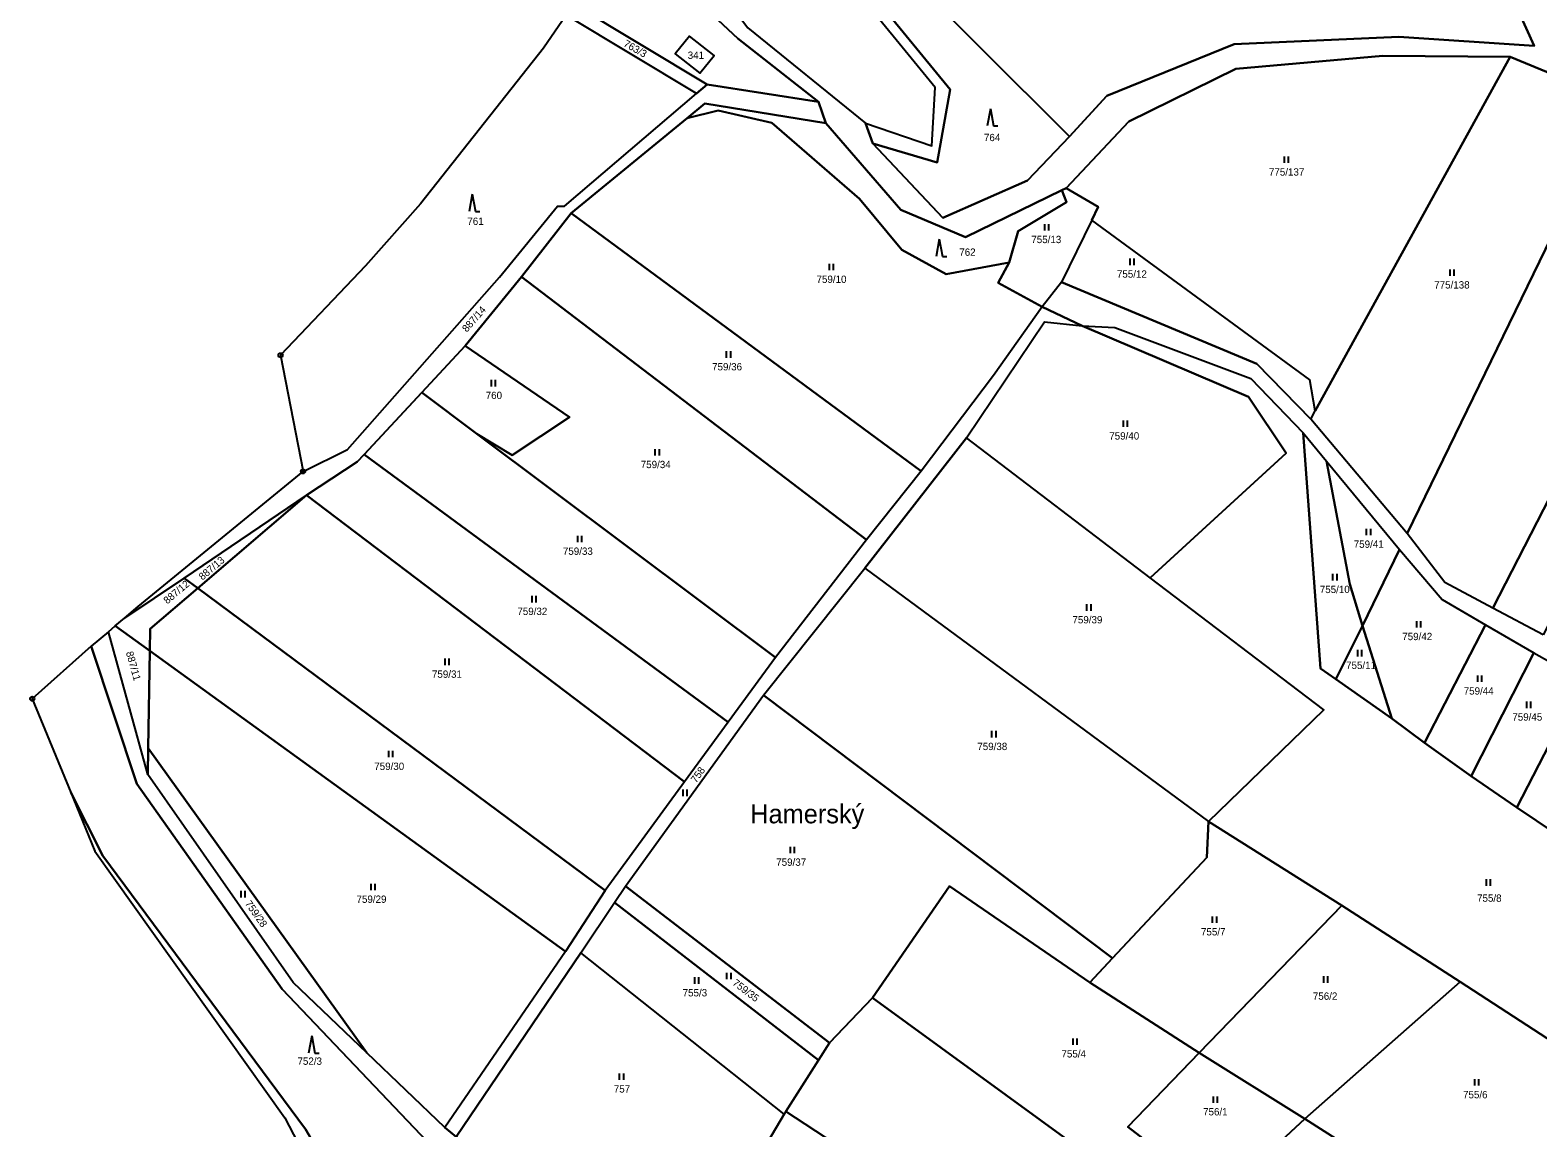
# Model space of a CAD drawing. Extents: x -654083 to -650132, y -1099819 to -1096699.
# Drawn here: x -653842.7 to -653492.6, y -1098231 to -1097976.1 of the extents above; entities that cross this region are included whole.
import ezdxf

# ---------------------------------------------------------------- set-up
doc = ezdxf.new("R2010")
doc.units = 0
for name, color, linetype in [('Geodetické body', 7, 'Continuous'), ('Názvy', 7, 'Continuous'), ('Obvody jako plochy', 7, 'Continuous'), ('Parcelní čísla', 7, 'Continuous'), ('Značky kultur', 7, 'Continuous')]:
    doc.layers.add(name, color=color, linetype=linetype)

msp = doc.modelspace()

# ---------------------------------------------------------------- linework, layer by layer
at = {"layer": 'Geodetické body'}
for centre, radius in [((-653784.54, -1098051.6), 0.5), ((-653784.54, -1098051.6), 0.001), ((-653779.31, -1098078.59), 0.5), ((-653779.31, -1098078.59), 0.001), ((-653842.18, -1098131.36), 0.5), ((-653842.18, -1098131.36), 0.001)]:
    msp.add_circle(centre, radius, dxfattribs=at)
at = {"layer": 'Obvody jako plochy'}
for points in [[(-653713.62, -1097930.33), (-653706.55, -1097940.57), (-653697.49, -1097947.08), (-653675.99, -1097975.54), (-653648.7, -1097997.71), (-653633.3, -1098002.98), (-653632.53, -1097989.46), (-653653.11, -1097964.2), (-653667.52, -1097949), (-653667.58, -1097933.88), (-653666.3, -1097931.63), (-653679.22, -1097917.1), (-653687.31, -1097908.47), (-653704.35, -1097912.36)], [(-653649.71, -1097952.26), (-653642.8, -1097959.41), (-653601.35, -1098000.78), (-653611.1, -1098011.02), (-653630.75, -1098019.66), (-653647, -1098002.44), (-653632.03, -1098006.86), (-653629.06, -1097989.93), (-653663.58, -1097947.68)], [(-653703.46, -1097954.62), (-653678.31, -1097978.03), (-653659.65, -1097992.78), (-653685.44, -1097988.72), (-653716.54, -1097970.07), (-653709.82, -1097960.08)], [(-653642.8, -1097959.41), (-653496.77, -1097972.37), (-653493.43, -1097979.77), (-653524.85, -1097977.7), (-653563.09, -1097979.4), (-653592.66, -1097991.35), (-653601.35, -1098000.78)], [(-653784.54, -1098051.6), (-653779.31, -1098078.59), (-653768.96, -1098073.49), (-653733.67, -1098033.51), (-653720.21, -1098016.99), (-653718.63, -1098017), (-653687.93, -1097990.83), (-653718.24, -1097972.6), (-653723.44, -1097980.32), (-653752.03, -1098016.42), (-653764.83, -1098030.84)], [(-653718.24, -1097972.6), (-653716.54, -1097970.07), (-653685.44, -1097988.72), (-653687.93, -1097990.83)], [(-653683.87, -1097982.01), (-653689.53, -1097977.49), (-653692.91, -1097981.61), (-653687.19, -1097986.07)], [(-653689.53, -1097977.49), (-653692.91, -1097981.61), (-653687.19, -1097986.07), (-653683.87, -1097982.01)], [(-653683.87, -1097982.01), (-653689.53, -1097977.49), (-653692.91, -1097981.61), (-653687.19, -1097986.07)], [(-653562.68, -1097985.1), (-653528.58, -1097982.07), (-653499, -1097982.28), (-653544.24, -1098064.55), (-653545.5, -1098057.32), (-653596.14, -1098020.25), (-653594.63, -1098017.16), (-653602.07, -1098012.79), (-653587.53, -1097997.31)], [(-653474.06, -1097992.64), (-653522.9, -1098093.01), (-653545.29, -1098066.46), (-653544.24, -1098064.55), (-653499, -1097982.28)], [(-653766.71, -1098076.38), (-653778.54, -1098084.12), (-653806.95, -1098103.34), (-653820.78, -1098112.69), (-653817.58, -1098109.96), (-653779.31, -1098078.59), (-653768.96, -1098073.49), (-653733.67, -1098033.51), (-653720.21, -1098016.99), (-653718.63, -1098017), (-653687.93, -1097990.83), (-653685.44, -1097988.72), (-653659.65, -1097992.78), (-653657.92, -1097997.75), (-653685.97, -1097993.14), (-653690.13, -1097996.58), (-653717.07, -1098018.65), (-653728.58, -1098033.36), (-653741.63, -1098049.4), (-653751.75, -1098060.24), (-653765.08, -1098074.62)], [(-653657.92, -1097997.75), (-653640.48, -1098017.81), (-653625.48, -1098024.2), (-653603.11, -1098013.28), (-653602.06, -1098016.08), (-653613.28, -1098022.81), (-653615.34, -1098030.08), (-653629.95, -1098032.79), (-653640.24, -1098027.1), (-653650.11, -1098015.27), (-653670.41, -1097997.63), (-653682.92, -1097994.74), (-653690.13, -1097996.58), (-653685.97, -1097993.14)], [(-653448.67, -1098004.49), (-653503.03, -1098110.31), (-653514.16, -1098104.36), (-653522.9, -1098093.01), (-653474.06, -1097992.64)], [(-653640.24, -1098027.1), (-653629.95, -1098032.79), (-653615.34, -1098030.08), (-653617.92, -1098034.79), (-653607.69, -1098040.36), (-653618.97, -1098056.31), (-653635.8, -1098078.5), (-653717.07, -1098018.65), (-653690.13, -1097996.58), (-653682.92, -1097994.74), (-653670.41, -1097997.63), (-653650.11, -1098015.27)], [(-653491.36, -1098116.55), (-653503.03, -1098110.31), (-653448.67, -1098004.49), (-653437.16, -1098010.24)], [(-653603.11, -1098013.28), (-653602.07, -1098012.79), (-653594.63, -1098017.16), (-653596.14, -1098020.25), (-653603.2, -1098034.64), (-653607.69, -1098040.36), (-653617.92, -1098034.79), (-653615.34, -1098030.08), (-653613.28, -1098022.81), (-653602.06, -1098016.08)], [(-653717.07, -1098018.65), (-653635.8, -1098078.5), (-653648.49, -1098094.45), (-653728.58, -1098033.36)], [(-653545.29, -1098066.46), (-653544.24, -1098064.55), (-653545.5, -1098057.32), (-653596.14, -1098020.25), (-653603.2, -1098034.64), (-653557.83, -1098053.58)], [(-653728.58, -1098033.36), (-653648.49, -1098094.45), (-653669.6, -1098121.79), (-653738.93, -1098069.85), (-653730.77, -1098074.77), (-653717.44, -1098065.97), (-653741.63, -1098049.4)], [(-653618.97, -1098056.31), (-653635.8, -1098078.5), (-653648.49, -1098094.45), (-653669.6, -1098121.79), (-653680.58, -1098136.79), (-653690.76, -1098150.69), (-653709.18, -1098175.93), (-653718.33, -1098190.03), (-653746.37, -1098230.94), (-653743.73, -1098233.12), (-653714.84, -1098190.36), (-653706.96, -1098178.69), (-653704.43, -1098174.89), (-653672.35, -1098130.56), (-653648.86, -1098101.05), (-653625.26, -1098070.79), (-653607.11, -1098043.87), (-653598.42, -1098044.74), (-653607.69, -1098040.36)], [(-653598.42, -1098044.74), (-653559.78, -1098061.29), (-653551.01, -1098074.32), (-653582.6, -1098103.32), (-653625.26, -1098070.79), (-653607.11, -1098043.87)], [(-653526.47, -1098135.95), (-653518.87, -1098141.6), (-653508.05, -1098149.35), (-653498.93, -1098155.64), (-653497.41, -1098156.63), (-653488.24, -1098162.8), (-653478.25, -1098170.57), (-653468.63, -1098177.08), (-653458.96, -1098184.59), (-653444.09, -1098197.38), (-653468.56, -1098224.39), (-653510.59, -1098197.1), (-653538.11, -1098179.34), (-653569.01, -1098159.89), (-653542.28, -1098133.96), (-653582.6, -1098103.32), (-653551.01, -1098074.32), (-653559.78, -1098061.29), (-653598.42, -1098044.74), (-653590.78, -1098045.19), (-653559.18, -1098057.02), (-653547.07, -1098069.66), (-653543, -1098124.32), (-653539.45, -1098126.81)], [(-653717.44, -1098065.97), (-653730.77, -1098074.77), (-653738.93, -1098069.85), (-653751.75, -1098060.24), (-653741.63, -1098049.4)], [(-653669.6, -1098121.79), (-653680.58, -1098136.79), (-653765.08, -1098074.62), (-653751.75, -1098060.24), (-653738.93, -1098069.85)], [(-653536.26, -1098104.78), (-653533.27, -1098114.41), (-653539.45, -1098126.81), (-653543, -1098124.32), (-653547.07, -1098069.66), (-653541.65, -1098076.21)], [(-653569.01, -1098159.89), (-653542.28, -1098133.96), (-653582.6, -1098103.32), (-653625.26, -1098070.79), (-653648.86, -1098101.05)], [(-653765.08, -1098074.62), (-653680.58, -1098136.79), (-653690.76, -1098150.69), (-653778.54, -1098084.12), (-653766.71, -1098076.38)], [(-653541.65, -1098076.21), (-653524.67, -1098096.75), (-653533.27, -1098114.41), (-653536.26, -1098104.78)], [(-653778.54, -1098084.12), (-653803.78, -1098105.68), (-653806.95, -1098103.34)], [(-653778.54, -1098084.12), (-653690.76, -1098150.69), (-653709.18, -1098175.93), (-653803.78, -1098105.68)], [(-653524.67, -1098096.75), (-653514.76, -1098108.32), (-653504.7, -1098114.18), (-653518.87, -1098141.6), (-653526.47, -1098135.95), (-653533.27, -1098114.41)], [(-653569.01, -1098159.89), (-653569.45, -1098168.26), (-653591.35, -1098191.64), (-653672.35, -1098130.56), (-653648.86, -1098101.05)], [(-653814.81, -1098115.11), (-653814.89, -1098120.27), (-653822.9, -1098114.47), (-653820.78, -1098112.69), (-653806.95, -1098103.34), (-653803.78, -1098105.68)], [(-653709.18, -1098175.93), (-653718.33, -1098190.03), (-653814.89, -1098120.27), (-653814.81, -1098115.11), (-653803.78, -1098105.68)], [(-653814.89, -1098120.27), (-653815.24, -1098142.84), (-653815.33, -1098148.98), (-653824.49, -1098115.81), (-653822.9, -1098114.47)], [(-653533.27, -1098114.41), (-653526.47, -1098135.95), (-653539.45, -1098126.81)], [(-653504.7, -1098114.18), (-653493.48, -1098120.72), (-653508.05, -1098149.35), (-653518.87, -1098141.6)], [(-653721.27, -1098267.91), (-653711.82, -1098254.28), (-653728.34, -1098247.4), (-653747.42, -1098237.45), (-653784.16, -1098198.82), (-653817.94, -1098151.09), (-653828.49, -1098119.16), (-653842.18, -1098131.36), (-653833.25, -1098153.1), (-653825.81, -1098167.82), (-653778.72, -1098231.33), (-653763.42, -1098257.49), (-653742.27, -1098284.25)], [(-653814.89, -1098120.27), (-653718.33, -1098190.03), (-653746.37, -1098230.94), (-653764.5, -1098213.59), (-653815.24, -1098142.84)], [(-653482.17, -1098127.04), (-653497.41, -1098156.63), (-653498.93, -1098155.64), (-653508.05, -1098149.35), (-653493.48, -1098120.72)], [(-653482.17, -1098127.04), (-653472.69, -1098132.34), (-653488.24, -1098162.8), (-653497.41, -1098156.63)], [(-653629.2, -1098174.91), (-653647.07, -1098200.83), (-653657.02, -1098211.29), (-653704.43, -1098174.89), (-653672.35, -1098130.56), (-653591.35, -1098191.64), (-653596.62, -1098197.26)], [(-653815.24, -1098142.84), (-653764.5, -1098213.59), (-653781.58, -1098197.23), (-653815.33, -1098148.98)], [(-653827.67, -1098166.73), (-653783.54, -1098228.67), (-653767.24, -1098260.09), (-653753.1, -1098273.36), (-653743.69, -1098285.49), (-653742.27, -1098284.25), (-653763.42, -1098257.49), (-653778.72, -1098231.33), (-653825.81, -1098167.82), (-653833.25, -1098153.1)], [(-653569.01, -1098159.89), (-653538.11, -1098179.34), (-653571.22, -1098213.59), (-653596.62, -1098197.26), (-653591.35, -1098191.64), (-653569.45, -1098168.26)], [(-653657.02, -1098211.29), (-653659.63, -1098215.26), (-653706.96, -1098178.69), (-653704.43, -1098174.89)], [(-653546.7, -1098228.92), (-653502.41, -1098257.19), (-653526.27, -1098282.15), (-653530.29, -1098285.81), (-653543.55, -1098284.07), (-653600.1, -1098235.04), (-653647.07, -1098200.83), (-653629.2, -1098174.91), (-653596.62, -1098197.26), (-653571.22, -1098213.59), (-653587.81, -1098230.74), (-653566.43, -1098247.25)], [(-653706.96, -1098178.69), (-653659.63, -1098215.26), (-653667.18, -1098227.19), (-653667.58, -1098227.83), (-653714.84, -1098190.36)], [(-653510.59, -1098197.1), (-653546.7, -1098228.92), (-653571.22, -1098213.59), (-653538.11, -1098179.34)], [(-653667.58, -1098227.83), (-653714.84, -1098190.36), (-653743.73, -1098233.12), (-653729.84, -1098242.69), (-653706.46, -1098252.31), (-653684.02, -1098255.61)], [(-653510.59, -1098197.1), (-653468.56, -1098224.39), (-653476.06, -1098232.31), (-653502.41, -1098257.19), (-653546.7, -1098228.92)], [(-653556.04, -1098300.72), (-653566.03, -1098298.04), (-653625.84, -1098254.28), (-653667.18, -1098227.19), (-653659.63, -1098215.26), (-653657.02, -1098211.29), (-653647.07, -1098200.83), (-653600.1, -1098235.04), (-653543.55, -1098284.07)], [(-653571.22, -1098213.59), (-653546.7, -1098228.92), (-653566.43, -1098247.25), (-653587.81, -1098230.74)], [(-653629.97, -1098294.65), (-653582.55, -1098325.18), (-653566.03, -1098298.04), (-653625.84, -1098254.28), (-653667.18, -1098227.19), (-653667.58, -1098227.83), (-653684.02, -1098255.61)]]:
    msp.add_lwpolyline(points, close=True, dxfattribs=at)
for points in [[(-653663.58, -1097947.68), (-653629.06, -1097989.93), (-653632.03, -1098006.86), (-653647, -1098002.44), (-653648.7, -1097997.71), (-653633.3, -1098002.98), (-653632.53, -1097989.46), (-653653.11, -1097964.2)], [(-653474.06, -1097992.64), (-653499, -1097982.28), (-653528.58, -1097982.07), (-653562.68, -1097985.1), (-653587.53, -1097997.31), (-653602.07, -1098012.79), (-653603.11, -1098013.28), (-653625.48, -1098024.2), (-653640.48, -1098017.81), (-653657.92, -1097997.75), (-653659.65, -1097992.78), (-653678.31, -1097978.03), (-653703.46, -1097954.62)], [(-653675.99, -1097975.54), (-653648.7, -1097997.71), (-653647, -1098002.44), (-653630.75, -1098019.66), (-653611.1, -1098011.02), (-653601.35, -1098000.78), (-653592.66, -1097991.35), (-653563.09, -1097979.4), (-653524.85, -1097977.7), (-653493.43, -1097979.77), (-653496.77, -1097972.37)], [(-653491.36, -1098116.55), (-653503.03, -1098110.31), (-653514.16, -1098104.36), (-653522.9, -1098093.01), (-653545.29, -1098066.46), (-653557.83, -1098053.58), (-653603.2, -1098034.64), (-653607.69, -1098040.36), (-653598.42, -1098044.74), (-653590.78, -1098045.19), (-653559.18, -1098057.02), (-653547.07, -1098069.66), (-653541.65, -1098076.21), (-653524.67, -1098096.75), (-653514.76, -1098108.32), (-653504.7, -1098114.18), (-653493.48, -1098120.72), (-653482.17, -1098127.04)], [(-653743.73, -1098233.12), (-653746.37, -1098230.94), (-653764.5, -1098213.59), (-653781.58, -1098197.23), (-653815.33, -1098148.98), (-653824.49, -1098115.81), (-653828.49, -1098119.16), (-653817.94, -1098151.09), (-653784.16, -1098198.82), (-653747.42, -1098237.45)]]:
    msp.add_lwpolyline(points, dxfattribs=at)
at = {"layer": 'Značky kultur'}
for p, q in [((-653619.69, -1097994.35), (-653620.43, -1097998.35)), ((-653619.69, -1097994.35), (-653618.96, -1097998.35)), ((-653618.96, -1097998.35), (-653617.96, -1097998.35)), ((-653551.48, -1098005.46), (-653551.48, -1098006.96)), ((-653550.45, -1098006.96), (-653550.45, -1098005.46)), ((-653740.01, -1098014.19), (-653740.74, -1098018.19)), ((-653740.01, -1098014.19), (-653739.28, -1098018.19)), ((-653739.28, -1098018.19), (-653738.28, -1098018.19)), ((-653607.15, -1098021.14), (-653607.15, -1098022.64)), ((-653606.12, -1098022.64), (-653606.12, -1098021.14)), ((-653631.56, -1098024.65), (-653632.3, -1098028.65)), ((-653631.56, -1098024.65), (-653630.83, -1098028.65)), ((-653630.83, -1098028.65), (-653629.83, -1098028.65)), ((-653657.13, -1098030.38), (-653657.13, -1098031.88)), ((-653656.1, -1098031.88), (-653656.1, -1098030.38)), ((-653587.29, -1098029.16), (-653587.29, -1098030.66)), ((-653586.27, -1098030.66), (-653586.27, -1098029.16)), ((-653513.04, -1098031.68), (-653513.04, -1098033.18)), ((-653512.02, -1098033.18), (-653512.02, -1098031.68)), ((-653681.02, -1098050.69), (-653681.02, -1098052.19)), ((-653679.99, -1098052.19), (-653679.99, -1098050.69)), ((-653735.6, -1098057.34), (-653735.6, -1098058.84)), ((-653734.58, -1098058.84), (-653734.58, -1098057.34)), ((-653588.84, -1098066.76), (-653588.84, -1098068.26)), ((-653587.82, -1098068.26), (-653587.82, -1098066.76)), ((-653697.59, -1098073.39), (-653697.59, -1098074.89)), ((-653696.57, -1098074.89), (-653696.57, -1098073.39)), ((-653715.59, -1098093.52), (-653715.59, -1098095.02)), ((-653714.57, -1098095.02), (-653714.57, -1098093.52)), ((-653532.4, -1098091.89), (-653532.4, -1098093.39)), ((-653531.38, -1098093.39), (-653531.38, -1098091.89)), ((-653540.22, -1098102.4), (-653540.22, -1098103.9)), ((-653539.2, -1098103.9), (-653539.2, -1098102.4)), ((-653726.17, -1098107.49), (-653726.17, -1098108.99)), ((-653725.15, -1098108.99), (-653725.15, -1098107.49)), ((-653597.34, -1098109.44), (-653597.34, -1098110.94)), ((-653596.32, -1098110.94), (-653596.32, -1098109.44)), ((-653520.76, -1098113.32), (-653520.76, -1098114.82)), ((-653519.73, -1098114.82), (-653519.73, -1098113.32)), ((-653746.38, -1098122.06), (-653746.38, -1098123.56)), ((-653745.35, -1098123.56), (-653745.35, -1098122.06)), ((-653534.45, -1098120.02), (-653534.45, -1098121.52)), ((-653533.43, -1098121.52), (-653533.43, -1098120.02)), ((-653506.56, -1098125.97), (-653506.56, -1098127.47)), ((-653505.54, -1098127.47), (-653505.54, -1098125.97)), ((-653495.22, -1098132.02), (-653495.22, -1098133.52)), ((-653494.2, -1098133.52), (-653494.2, -1098132.02)), ((-653619.41, -1098138.85), (-653619.41, -1098140.35)), ((-653618.39, -1098140.35), (-653618.39, -1098138.85)), ((-653759.45, -1098143.47), (-653759.45, -1098144.97)), ((-653758.43, -1098144.97), (-653758.43, -1098143.47)), ((-653691.13, -1098152.48), (-653691.13, -1098153.98)), ((-653690.1, -1098153.98), (-653690.1, -1098152.48)), ((-653666.17, -1098165.73), (-653666.17, -1098167.23)), ((-653665.15, -1098167.23), (-653665.15, -1098165.73)), ((-653763.6, -1098174.32), (-653763.6, -1098175.82)), ((-653762.58, -1098175.82), (-653762.58, -1098174.32)), ((-653504.56, -1098173.29), (-653504.56, -1098174.79)), ((-653503.54, -1098174.79), (-653503.54, -1098173.29)), ((-653793.76, -1098175.99), (-653793.76, -1098177.49)), ((-653792.73, -1098177.49), (-653792.73, -1098175.99)), ((-653568.17, -1098181.9), (-653568.17, -1098183.4)), ((-653567.15, -1098183.4), (-653567.15, -1098181.9)), ((-653688.43, -1098196.05), (-653688.43, -1098197.55)), ((-653687.41, -1098197.55), (-653687.41, -1098196.05)), ((-653680.95, -1098195.02), (-653680.95, -1098196.52)), ((-653679.93, -1098196.52), (-653679.93, -1098195.02)), ((-653542.38, -1098195.82), (-653542.38, -1098197.32)), ((-653541.35, -1098197.32), (-653541.35, -1098195.82)), ((-653777.29, -1098209.66), (-653778.03, -1098213.66)), ((-653777.29, -1098209.66), (-653776.56, -1098213.66)), ((-653600.53, -1098210.24), (-653600.53, -1098211.74)), ((-653599.51, -1098211.74), (-653599.51, -1098210.24)), ((-653776.56, -1098213.66), (-653775.56, -1098213.66)), ((-653705.87, -1098218.39), (-653705.87, -1098219.89)), ((-653704.84, -1098219.89), (-653704.84, -1098218.39)), ((-653507.28, -1098219.71), (-653507.28, -1098221.21)), ((-653506.26, -1098221.21), (-653506.26, -1098219.71)), ((-653567.99, -1098223.69), (-653567.99, -1098225.19)), ((-653566.96, -1098225.19), (-653566.96, -1098223.69))]:
    msp.add_line(p, q, dxfattribs=at)

# ---------------------------------------------------------------- texts
at = {"layer": 'Názvy'}
msp.add_text('Hamerský', height=4.4, dxfattribs=at).set_placement((-653675.46, -1098160.3))
at = {"layer": 'Parcelní čísla'}
for s, rotation, p in [('763/3', 330.363, (-653705.05, -1097979.74)), ('887/14', 48.69, (-653741.27, -1098046.37)), ('887/13', 40.347, (-653802.66, -1098103.95)), ('887/12', 40.059, (-653810.84, -1098109.48)), ('887/11', 285.75, (-653820.46, -1098120.63)), ('758', 54.351, (-653688.04, -1098151.05)), ('759/28', 305.109, (-653792.88, -1098178.94)), ('759/35', 322.596, (-653679.74, -1098197.66))]:
    msp.add_text(s, height=1.7, rotation=rotation, dxfattribs=at).set_placement(p)
for s, p in [('341', (-653689.98, -1097982.79)), ('764', (-653621.19, -1098001.89)), ('775/137', (-653555.01, -1098009.89)), ('761', (-653741.16, -1098021.34)), ('755/13', (-653610.19, -1098025.57)), ('762', (-653626.92, -1098028.51)), ('755/12', (-653590.31, -1098033.59)), ('759/10', (-653660.07, -1098034.81)), ('775/138', (-653516.63, -1098036.11)), ('759/36', (-653684.32, -1098055.12)), ('760', (-653736.89, -1098061.78)), ('759/40', (-653592.09, -1098071.19)), ('759/34', (-653700.89, -1098077.82)), ('759/41', (-653535.32, -1098096.32)), ('759/33', (-653718.97, -1098097.95)), ('755/10', (-653543.2, -1098106.83)), ('759/32', (-653729.54, -1098111.92)), ('759/39', (-653600.64, -1098113.87)), ('759/42', (-653524.05, -1098117.76)), ('755/11', (-653537.1, -1098124.46)), ('759/31', (-653749.37, -1098126.5)), ('759/44', (-653509.78, -1098130.4)), ('759/45', (-653498.49, -1098136.45)), ('759/38', (-653622.73, -1098143.29)), ('759/30', (-653762.77, -1098147.9)), ('759/37', (-653669.43, -1098170.16)), ('759/29', (-653766.89, -1098178.76)), ('755/8', (-653506.68, -1098178.51)), ('755/7', (-653570.79, -1098186.33)), ('755/3', (-653691.16, -1098200.49)), ('756/2', (-653544.81, -1098201.27)), ('755/4', (-653603.19, -1098214.67)), ('752/3', (-653780.6, -1098216.37)), ('757', (-653707.15, -1098222.82)), ('755/6', (-653509.94, -1098224.14)), ('756/1', (-653570.3, -1098228.12))]:
    msp.add_text(s, height=1.7, dxfattribs=at).set_placement(p)

doc.saveas('drawing.dxf')
